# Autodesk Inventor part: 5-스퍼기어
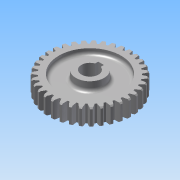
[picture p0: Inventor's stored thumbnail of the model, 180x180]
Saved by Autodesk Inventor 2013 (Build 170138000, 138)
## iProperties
Created: 2013-08
Part Number: 5-스퍼기어
Material: 강
Document SubType Name: Modeling
Designer: 한국산업디자인학원
Categories: <?xml version="1.0" encoding="UTF-16"?> <MemberInstance><Categories><FamilyTemplate><FamilyTemplateParameter ValueType="xs:double" Id="1" ObjectReferenceKey="da
Density: 1 g/cm^3
CustomPartVersion: 1
Author: 한국산업디자인학원
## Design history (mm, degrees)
sketch "Sketch1"
  geometry: C1 r 37 at (0, 0)
  constraints: 1 centre point
  dimensions: "d0" = 74 diameter of C1 (= da_da)
extrude "Extrusion1" new body sketch "Sketch1" distance "d1" = 15 (= da_b); taper "d2" = 0 deg
chamfer "모따기1" distance "d49" = 1; stored, may be unused: second distance "d50" = 2, angle "d51" = 45 deg
workplane "Work Plane2"
feature "피치 지름" dims "d4" = 10, "d5" = 0
workplane "Work Plane8"
workplane "Work Plane9"
feature "스퍼 기어" dims "da_b" = 15, "da_d" = 70, "da_aw" = 70, "da_da" = 74, "da_df" = 65, "da_dw" = 70, angle "da_beta" = 0 deg, "da_lefttooth" = 0, "da_righttooth" = 0
sketch "스케치5"
  geometry: C1 r 27.5 at (0, 0); C2 r 12.5 at (0, 0); A1 r 36 centre (0, 0) between (-5.215, 35.62) and (-7.633, 35.181) reference
  constraints: 2 centre point, 2 coincident
  dimensions: "d65" = 55 diameter of C1; "d67" = 25 diameter of C2
extrude "돌출4" cut sketch "스케치5" distance "d68" = 5; taper "d69" = 0 deg
sketch "스케치3"
  geometry: C1 r 12.5 at (0, 0) reference
extrude "돌출2" join sketch "스케치3" distance "d55" = 3; taper "d57" = 0 deg; dims "d56" = 28, "d58" = 0
fillet "모깎기1" dims "d70" = 3
sketch "스케치6"
  geometry: L1 (-2.5, 7.071)-(-2.5, 9.8); L2 (-2.5, 9.8)-(2.5, 9.8); L3 (2.5, 9.8)-(2.5, 7.071); C1 r 12.5 at (0, 0) reference; A1 r 7.5 centre (0, 0) between (-2.5, 7.071) and (2.5, 7.071); 1 further point
  constraints: 6 end point, 2 parallel, 2 point on circle, 1 centre point, 1 horizontal, 1 midpoint, 1 vertical, 1 vertical alignment
  dimensions: "d71" = 15 diameter of A1; "d73" = 5 distance of L1.end L2.end; "d74" = 17.3 dimension on A1 L2
extrude "돌출5" cut sketch "스케치6" stored distance "d75" = 10; taper "d76" = 0 deg
body "Solid1"
mirror "대칭1"
sketch "Sketch2"
  geometry: C1 r 37 at (0, 0) reference; C2 r 35 at (0, 0)
  constraints: 1 centre point, 1 coincident
  dimensions: "d3" = 70 diameter of C2 (= da_dw)
body "Srf1"
other parameters: "d17" = 0, "d34" = 0.8976 (computed from da_z), "d39" = 0, "d41" = 0, "d47" = 0, "d48" = 0
